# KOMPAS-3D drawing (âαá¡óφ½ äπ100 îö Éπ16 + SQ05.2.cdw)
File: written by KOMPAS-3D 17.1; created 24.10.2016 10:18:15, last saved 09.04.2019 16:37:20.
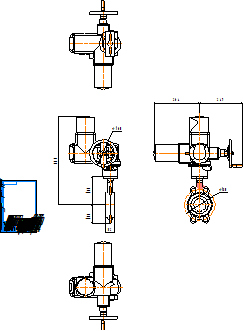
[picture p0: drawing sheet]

Sheet 1: A4, portrait

Title block, sheet 1: name: Гранвэл Ду100 МФ Ру16 + / SQ05.2; material: Внимание! Данный продукт является объектом авторского права ООО «Торговый Дом АДЛ». / Запрещается изменение, копирование, распространение / (в том числе путем копирования на другие сайты и ресурсы в Интернете) / или любое иное использование информации и объектов без предварительного / согласия правообладателя (ООО «Торговый Дом АДЛ»).; mass: 25,9; sheets: 1; organisation: ООО "Торговый дом АДЛ"; sheet format: A4; stored path: \\adlc.lan\data\АДЛ_ПКД\3D-модели\ADL production\Дисковые поворотные затворы ГРАНВЭЛ\межфланцевый с эл.приводом Auma Ру 16\KOMPAS 2D\Гранвэл Ду100 МФ Ру16 + SQ05.2.cdw

Views: Вид 1, Проекционный вид 3, Проекционный вид 4
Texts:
  Klimkovich
  ADL
Dimensions and other numbers on the sheet: 52; 509; 160; 165; 106; 1:1; 1; 25,9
